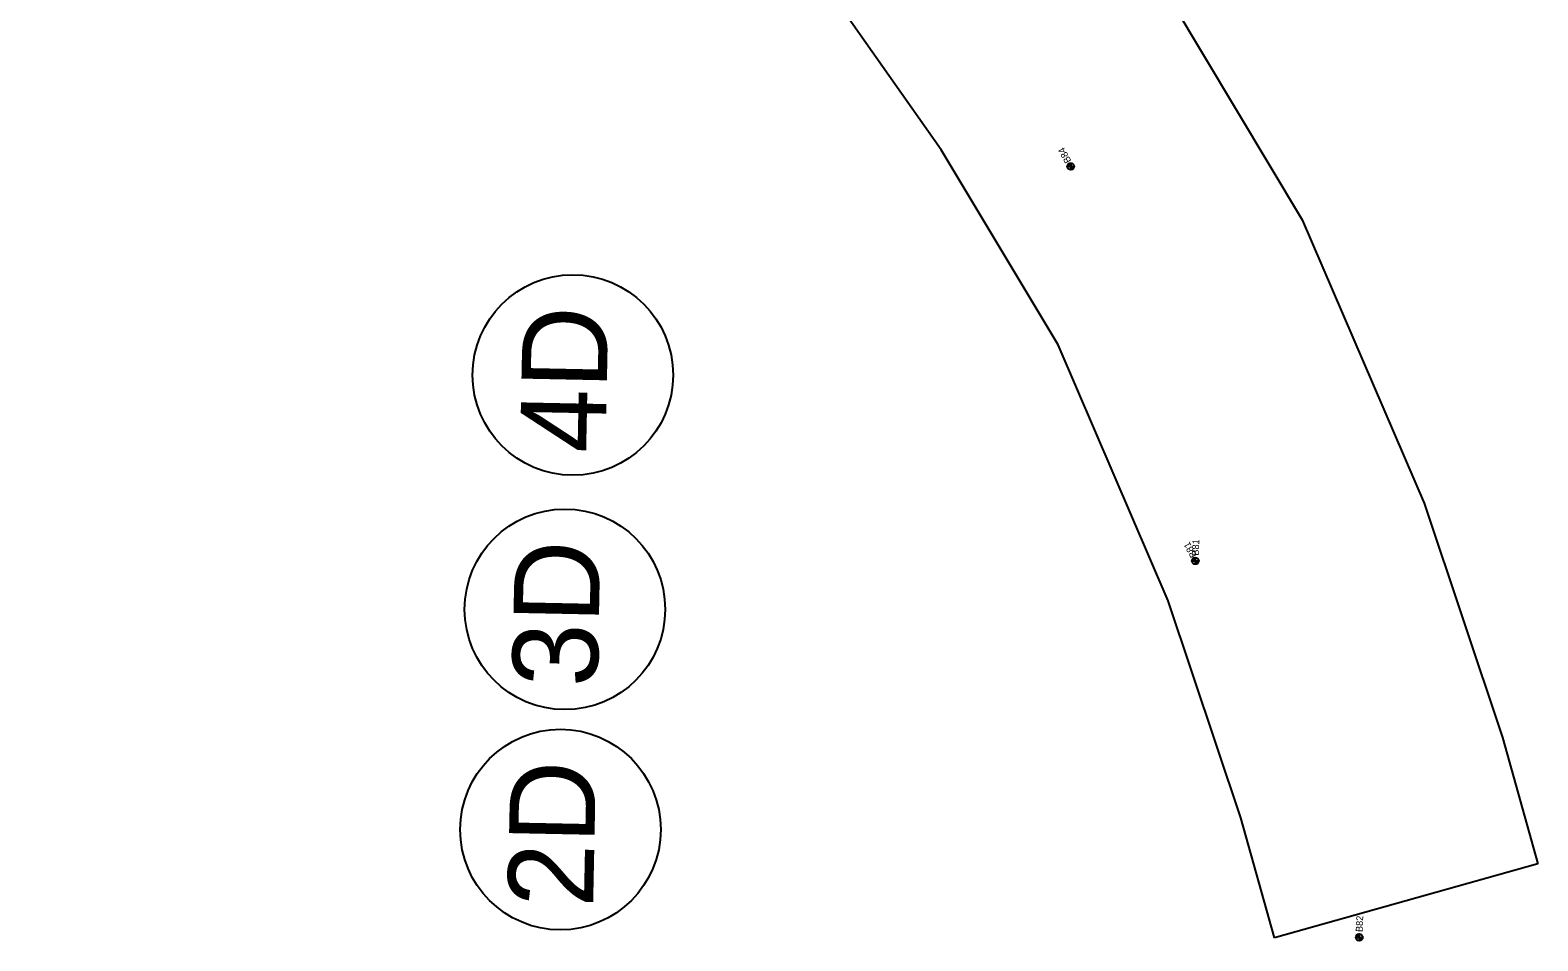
# Model space of a CAD drawing. Extents: x 327762 to 372792, y 127949 to 259367.
# Drawn here: x 358114 to 360318, y 175431 to 176762 of the extents above; entities that cross this region are included whole.
import ezdxf

# ---------------------------------------------------------------- set-up
doc = ezdxf.new("R2010")
doc.units = 0
for name, color, linetype in [('CA-TEXT', 7, 'Continuous'), ('E_SOIL_BORE1 [KAPUR_CADDS_LEVELS]', 7, 'Continuous'), ('E_SOIL_BORE2 [KAPUR_CADDS_LEVELS]', 7, 'Continuous'), ('P_MARK', 7, 'Continuous'), ('P_TC', 7, 'Continuous')]:
    doc.layers.add(name, color=color, linetype=linetype)

msp = doc.modelspace()

# ---------------------------------------------------------------- linework, layer by layer
at = {"layer": 'CA-TEXT'}
for centre in [(358907.5, 176257.6), (358895.9, 175915.1), (358889.4, 175593.2)]:
    msp.add_circle(centre, 146.6, dxfattribs=at)
at = {"layer": 'P_MARK'}
for p, q in [((359630.4, 176562.4), (359640.4, 176562.4)), ((359635.4, 176567.4), (359635.4, 176557.4)), ((359817.5, 175990.9), (359817.5, 175980.9)), ((359812.5, 175985.9), (359822.5, 175985.9)), ((360057.2, 175440.6), (360057.2, 175430.6)), ((360052.2, 175435.6), (360062.2, 175435.6))]:
    msp.add_line(p, q, dxfattribs=at)
for centre in [(359635.4, 176562.4), (359817.5, 175985.9), (360057.2, 175435.6)]:
    msp.add_circle(centre, 5, dxfattribs=at)
for centre, radius, start, end in [((359635.4, 176562.4), 4.5, 89.9869, 179.9869), ((359635.4, 176562.4), 4, 89.9869, 179.9869), ((359635.4, 176562.4), 3.5, 89.9869, 179.9869), ((359635.4, 176562.4), 3, 89.9869, 179.9869), ((359635.4, 176562.4), 2.5, 89.9869, 179.9869), ((359635.4, 176562.4), 2, 89.9869, 179.9869), ((359635.4, 176562.4), 1.5, 89.9869, 179.9869), ((359635.4, 176562.4), 1, 89.9869, 179.9869), ((359635.4, 176562.4), 0.5, 89.9869, 179.9869), ((359635.4, 176562.4), 4.5, 269.9869, 359.9869), ((359635.4, 176562.4), 4, 269.9869, 359.9869), ((359635.4, 176562.4), 3.5, 269.9869, 359.9869), ((359635.4, 176562.4), 3, 269.9869, 359.9869), ((359635.4, 176562.4), 2.5, 269.9869, 359.9869), ((359635.4, 176562.4), 2, 269.9869, 359.9869), ((359635.4, 176562.4), 1.5, 269.9869, 359.9869), ((359635.4, 176562.4), 1, 269.9869, 359.9869), ((359635.4, 176562.4), 0.5, 269.9869, 359.9869), ((359817.5, 175985.9), 4.5, 89.9869, 179.9869), ((359817.5, 175985.9), 4, 89.9869, 179.9869), ((359817.5, 175985.9), 3.5, 89.9869, 179.9869), ((359817.5, 175985.9), 3, 89.9869, 179.9869), ((359817.5, 175985.9), 2.5, 89.9869, 179.9869), ((359817.5, 175985.9), 2, 89.9869, 179.9869), ((359817.5, 175985.9), 1.5, 89.9869, 179.9869), ((359817.5, 175985.9), 1, 89.9869, 179.9869), ((359817.5, 175985.9), 0.5, 89.9869, 179.9869), ((359817.5, 175985.9), 4.5, 269.9869, 359.9869), ((359817.5, 175985.9), 4, 269.9869, 359.9869), ((359817.5, 175985.9), 3.5, 269.9869, 359.9869), ((359817.5, 175985.9), 3, 269.9869, 359.9869), ((359817.5, 175985.9), 2.5, 269.9869, 359.9869), ((359817.5, 175985.9), 2, 269.9869, 359.9869), ((359817.5, 175985.9), 1.5, 269.9869, 359.9869), ((359817.5, 175985.9), 1, 269.9869, 359.9869), ((359817.5, 175985.9), 0.5, 269.9869, 359.9869), ((360057.2, 175435.6), 4.5, 89.9869, 179.9869), ((360057.2, 175435.6), 4, 89.9869, 179.9869), ((360057.2, 175435.6), 3.5, 89.9869, 179.9869), ((360057.2, 175435.6), 3, 89.9869, 179.9869), ((360057.2, 175435.6), 2.5, 89.9869, 179.9869), ((360057.2, 175435.6), 2, 89.9869, 179.9869), ((360057.2, 175435.6), 1.5, 89.9869, 179.9869), ((360057.2, 175435.6), 1, 89.9869, 179.9869), ((360057.2, 175435.6), 0.5, 89.9869, 179.9869), ((360057.2, 175435.6), 4.5, 269.9869, 359.9869), ((360057.2, 175435.6), 4, 269.9869, 359.9869), ((360057.2, 175435.6), 3.5, 269.9869, 359.9869), ((360057.2, 175435.6), 3, 269.9869, 359.9869), ((360057.2, 175435.6), 2.5, 269.9869, 359.9869), ((360057.2, 175435.6), 2, 269.9869, 359.9869), ((360057.2, 175435.6), 1.5, 269.9869, 359.9869), ((360057.2, 175435.6), 1, 269.9869, 359.9869), ((360057.2, 175435.6), 0.5, 269.9869, 359.9869)]:
    msp.add_arc(centre, radius, start, end, dxfattribs=at)
at = {"layer": 'P_TC'}
msp.add_line((360318.3, 175542.9), (359933.1, 175435.2), dxfattribs=at)
for points in [[(356010.7, 184791.4), (356404.2, 181123.3), (356466.9, 180787.9), (356513.6, 180550.2), (356602.1, 180279.7), (356741, 179932.9), (356921, 179635), (357119.9, 179365.3), (357302.9, 179137.3), (357638, 178834.1), (357970.9, 178543), (358585.9, 178064.8), (358972.8, 177765.7), (359287.4, 177446.4), (359568.2, 177108.6), (359781.6, 176804.9), (359973.6, 176484.4), (360151.9, 176070.5), (360266.6, 175727.9), (360318.3, 175542.9)], [(359933.1, 175435.2), (359884.1, 175610.5), (359777.9, 175927.7), (359616.8, 176301.7), (359446, 176586.9), (359250.3, 176865.3), (358990.6, 177177.7), (358706.9, 177465.7), (358340.8, 177748.6), (357716.2, 178234.3), (357372.1, 178535.2), (357010.9, 178862.1), (356802.9, 179121.3), (356588.2, 179412.3), (356381.8, 179753.9), (356226, 180143), (356125.8, 180449.1), (356074, 180712.7), (356008.1, 181065.2), (355612.9, 184748.7)]]:
    msp.add_lwpolyline(points, dxfattribs=at)

# ---------------------------------------------------------------- texts
at = {"layer": 'CA-TEXT'}
for s, p in [('4D', (358955.2, 176143.2)), ('3D', (358943.6, 175800.8)), ('2D', (358937.1, 175478.9))]:
    msp.add_text(s, height=124.99, rotation=88.8468, dxfattribs=at).set_placement(p)
at = {"layer": 'E_SOIL_BORE1 [KAPUR_CADDS_LEVELS]'}
for s, p in [('B84', (359636.6, 176570.6)), ('B81', (359820.1, 175993.9))]:
    msp.add_text(s, height=10, rotation=118.6843, dxfattribs=at).set_placement(p)
at = {"layer": 'E_SOIL_BORE2 [KAPUR_CADDS_LEVELS]'}
for s, p in [('B81', (359822.4, 175993.4)), ('B82', (360062, 175443.3))]:
    msp.add_text(s, height=10, rotation=87.2646, dxfattribs=at).set_placement(p)

doc.saveas('drawing.dxf')
